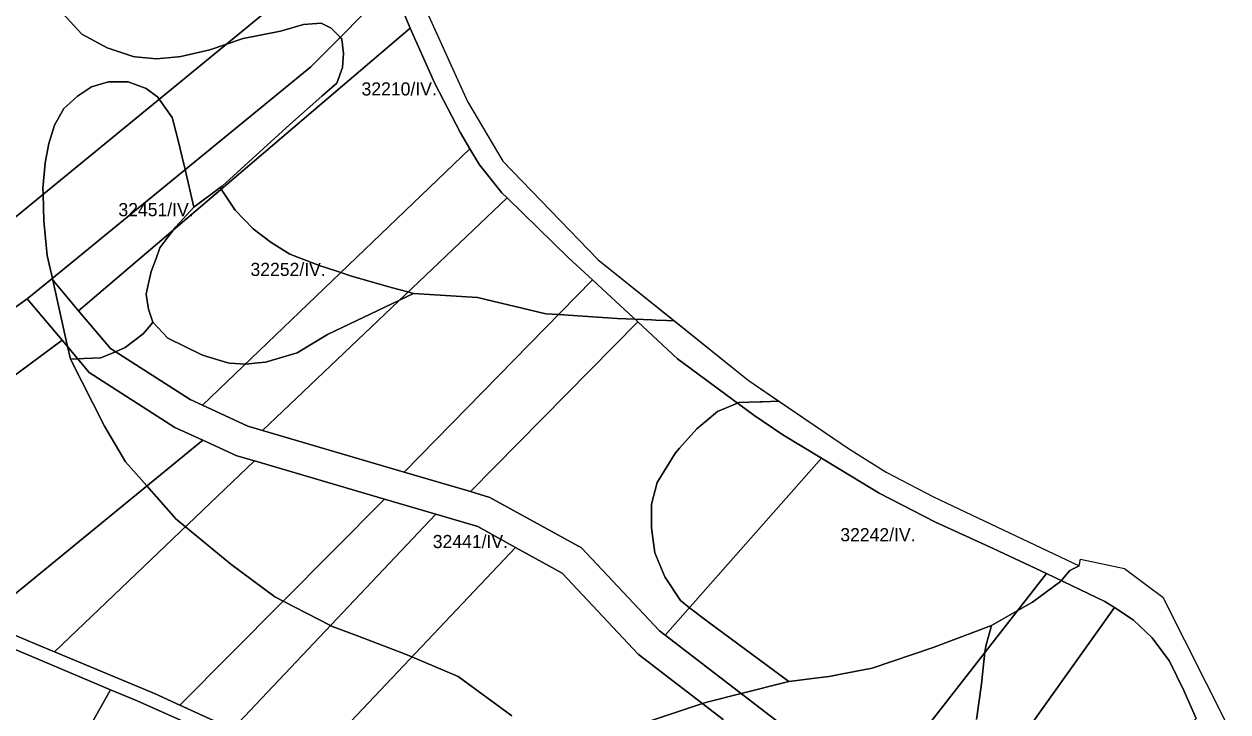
# Model space of a CAD drawing. Extents: x -522079 to -518833, y -1142400 to -1139961.
# Drawn here: x -520002.4 to -519544.3, y -1140913.1 to -1140651.2 of the extents above; entities that cross this region are included whole.
import ezdxf

# ---------------------------------------------------------------- set-up
doc = ezdxf.new("R2010")
doc.units = 0
for name, color, linetype in [('95560013', 7, 'Continuous'), ('95610013', 7, 'Continuous'), ('95640013', 7, 'Continuous'), ('95660013', 7, 'Continuous')]:
    doc.layers.add(name, color=color, linetype=linetype)

msp = doc.modelspace()

# ---------------------------------------------------------------- linework, layer by layer
at = {"layer": '95560013'}
for points in [[(-519911.88, -1140647.84), (-520013.2, -1140730.8), (-520072.01, -1140664.71), (-520082.56, -1140649.64), (-519886.24, -1140527.38), (-519882.2, -1140547.1), (-519878.23, -1140567.62), (-519875.11, -1140585.42), (-519873.69, -1140593.69), (-519873.07, -1140596.47), (-519870.83, -1140606.54)], [(-519862.3, -1140636.3), (-519855.49, -1140652.85), (-519981.63, -1140760.4), (-519991.87, -1140748.27), (-519893.23, -1140667.47)], [(-519981.63, -1140760.4), (-519855.49, -1140652.85), (-519846.13, -1140673.83), (-519836.32, -1140692.64), (-519832.73, -1140698.73), (-519934.47, -1140796.36), (-519939.19, -1140794.19), (-519969.55, -1140774.7)], [(-519832.73, -1140698.73), (-519829.11, -1140704.83), (-519820.55, -1140715.47), (-519818.61, -1140717.36), (-519911.71, -1140805.9), (-519917.19, -1140804.28), (-519934.47, -1140796.36)], [(-519911.71, -1140805.9), (-519818.61, -1140717.36), (-519795.23, -1140740.19), (-519786.12, -1140748.61), (-519857.7, -1140821.8)], [(-519857.7, -1140821.8), (-519786.12, -1140748.61), (-519782.42, -1140752.04), (-519768.84, -1140764.57), (-519832.56, -1140829.21)], [(-520001.24, -1140755.77), (-519987.93, -1140771.54), (-520091.34, -1140848.28), (-520106.23, -1140841.79), (-520119.77, -1140834.99), (-520068.52, -1140802.68), (-520010.06, -1140762.16)], [(-519698.98, -1140816.54), (-519758.42, -1140883.91), (-519760.64, -1140882.2), (-519790.25, -1140850.67), (-519825.13, -1140831.39), (-519832.56, -1140829.21), (-519768.84, -1140764.57), (-519753.73, -1140778.67), (-519724.7, -1140800.07), (-519713.71, -1140807.66)], [(-520091.34, -1140848.28), (-519987.93, -1140771.54), (-519977.56, -1140783.82), (-519944.96, -1140804.75), (-519934.39, -1140809.6), (-520018.57, -1140878.52), (-520022.3, -1140876.95), (-520034.41, -1140872.06), (-520067.09, -1140858.86)], [(-519934.39, -1140809.6), (-519921.41, -1140815.55), (-519914.69, -1140817.53), (-519990.79, -1140890.22), (-519997.49, -1140887.4), (-520018.57, -1140878.52)], [(-519758.42, -1140883.91), (-519698.98, -1140816.54), (-519677.02, -1140829.78), (-519655.55, -1140840.89), (-519633.63, -1140850.83), (-519613.39, -1140860.38), (-519678.04, -1140943.34), (-519697.68, -1140930.5)], [(-519990.79, -1140890.22), (-519914.69, -1140817.53), (-519865.19, -1140832.11), (-519943.08, -1140910.55), (-519952.82, -1140906.1)], [(-519865.19, -1140832.11), (-519845.71, -1140837.84), (-519923.13, -1140919.66), (-519943.08, -1140910.55)], [(-519923.13, -1140919.66), (-519845.71, -1140837.84), (-519829.78, -1140842.53), (-519815.37, -1140850.5), (-519893.61, -1140933.19), (-519907.29, -1140926.89)], [(-519815.37, -1140850.5), (-519797.7, -1140860.26), (-519768.72, -1140891.13), (-519736.43, -1140915.9), (-519792.75, -1140975.43), (-519809.71, -1140968.63), (-519858.03, -1140948.23), (-519890.83, -1140934.46), (-519893.61, -1140933.19)], [(-519654.13, -1140967.02), (-519587.52, -1140873.31), (-519580.34, -1140878), (-519573.15, -1140884.93), (-519566.48, -1140893.71), (-519561.03, -1140904.86), (-519556.41, -1140915.6), (-519632.87, -1140997.67), (-519645.74, -1140981.03)]]:
    msp.add_lwpolyline(points, close=True, dxfattribs=at)
at = {"layer": '95610013'}
for points in [[(-519862.3, -1140636.3), (-519893.23, -1140667.47), (-519991.87, -1140748.27), (-520001.24, -1140755.77), (-520010.06, -1140762.16), (-520068.52, -1140802.68), (-520119.77, -1140834.99), (-520149.6, -1140820.02), (-520083.41, -1140780.15), (-520025.44, -1140739.97), (-520022.9, -1140738.15), (-520013.2, -1140730.8), (-519911.88, -1140647.84), (-519870.83, -1140606.54), (-519868.76, -1140615.85)], [(-519587.52, -1140873.31), (-519654.13, -1140967.02), (-519662.03, -1140953.81), (-519678.04, -1140943.34), (-519613.39, -1140860.38), (-519591.11, -1140871.05)], [(-520022.73, -1140882.19), (-519999.48, -1140892), (-519969.45, -1140904.62), (-520002.28, -1140962.91), (-520009.84, -1140957.29), (-520015.17, -1140949.95), (-520029.76, -1140941.98), (-520046.33, -1140932.29), (-520051.93, -1140931.48), (-520055.67, -1140929.56)], [(-519969.45, -1140904.62), (-519959.29, -1140908.89), (-519927.83, -1140922.94), (-519916.21, -1140928.63), (-519943.51, -1140985.08), (-519947.03, -1140986.05), (-519959.93, -1140985.31), (-519965.47, -1140973.69), (-519974.08, -1140974.02), (-519986.94, -1140971.3), (-519999.3, -1140964.63), (-520002.28, -1140962.91)]]:
    msp.add_lwpolyline(points, close=True, dxfattribs=at)
at = {"layer": '95640013'}
for points in [[(-519855.18, -1140633.03), (-519833.7, -1140680.7), (-519820.17, -1140703.4), (-519783.91, -1140740.96), (-519726.89, -1140786.75), (-519688.67, -1140812.79), (-519674.4, -1140821.79), (-519656.36, -1140831.22), (-519600.86, -1140857.49), (-519600.42, -1140854.95), (-519583.72, -1140858.5), (-519575.54, -1140864.6), (-519569.14, -1140869.38), (-519544.31, -1140918.54)], [(-519556.41, -1140915.6), (-519561.03, -1140904.86), (-519566.48, -1140893.71), (-519573.15, -1140884.93), (-519580.34, -1140878), (-519587.52, -1140873.31), (-519591.11, -1140871.05), (-519613.39, -1140860.38), (-519633.63, -1140850.83), (-519655.55, -1140840.89), (-519677.02, -1140829.78), (-519698.98, -1140816.54), (-519713.71, -1140807.66), (-519724.7, -1140800.07), (-519753.73, -1140778.67), (-519768.84, -1140764.57), (-519782.42, -1140752.04), (-519786.12, -1140748.61), (-519795.23, -1140740.19), (-519818.61, -1140717.36), (-519820.55, -1140715.47), (-519829.11, -1140704.83), (-519832.73, -1140698.73), (-519836.32, -1140692.64), (-519846.13, -1140673.83), (-519855.49, -1140652.85), (-519862.3, -1140636.3)], [(-519736.43, -1140915.9), (-519768.72, -1140891.13), (-519797.7, -1140860.26), (-519815.37, -1140850.5), (-519829.78, -1140842.53), (-519845.71, -1140837.84), (-519865.19, -1140832.11), (-519914.69, -1140817.53), (-519921.41, -1140815.55), (-519934.39, -1140809.6), (-519944.96, -1140804.75), (-519977.56, -1140783.82), (-519987.93, -1140771.54), (-520001.24, -1140755.77), (-519991.87, -1140748.27), (-519981.63, -1140760.4), (-519969.55, -1140774.7), (-519939.19, -1140794.19), (-519934.47, -1140796.36), (-519917.19, -1140804.28), (-519911.71, -1140805.9), (-519857.7, -1140821.8), (-519832.56, -1140829.21), (-519825.13, -1140831.39), (-519790.25, -1140850.67), (-519760.64, -1140882.2), (-519758.42, -1140883.91), (-519697.68, -1140930.5)], [(-520018.57, -1140878.52), (-519997.49, -1140887.4), (-519990.79, -1140890.22), (-519952.82, -1140906.1), (-519943.08, -1140910.55), (-519923.13, -1140919.66)], [(-519927.83, -1140922.94), (-519959.29, -1140908.89), (-519969.45, -1140904.62), (-519999.48, -1140892), (-520022.73, -1140882.19)]]:
    msp.add_lwpolyline(points, dxfattribs=at)
at = {"layer": '95660013'}
for points in [[(-519855.18, -1140633.03), (-519839.36, -1140668.14), (-519833.7, -1140680.7), (-519820.17, -1140703.4), (-519783.91, -1140740.96), (-519754.92, -1140764.24), (-519757.79, -1140764.12), (-519761.97, -1140763.94), (-519763.7, -1140763.87), (-519769.86, -1140763.63), (-519776.69, -1140763.36), (-519799.05, -1140761.83), (-519803.86, -1140761.5), (-519829.8, -1140755.31), (-519854.23, -1140753.74), (-519856.3, -1140753.2), (-519862.74, -1140751.53), (-519878.13, -1140747.12), (-519881.86, -1140745.87), (-519888.11, -1140743.78), (-519889.68, -1140743.26), (-519901.22, -1140738.85), (-519908.36, -1140734.44), (-519915.23, -1140729.2), (-519922.1, -1140722.03), (-519927.37, -1140714.14), (-519927.8, -1140713.5), (-519927.05, -1140712.94), (-519901.22, -1140689.5), (-519889.13, -1140678.75), (-519883.36, -1140673.79), (-519881.16, -1140667.73), (-519880.88, -1140662.49), (-519881.43, -1140656.97), (-519882.12, -1140656.28), (-519885.55, -1140652.84), (-519889.4, -1140650.91), (-519896, -1140651.46), (-519904.79, -1140653.94), (-519919.08, -1140656.7), (-519925.38, -1140658.9), (-519931.72, -1140661.11), (-519942.72, -1140663.59), (-519943.73, -1140663.68), (-519952.06, -1140664.42), (-519960.12, -1140663.66), (-519960.85, -1140663.59), (-519970.75, -1140660.28), (-519980.36, -1140655.04), (-519987.78, -1140647.05)], [(-519987.78, -1140647.05), (-519980.36, -1140655.04), (-519970.75, -1140660.28), (-519960.85, -1140663.59), (-519960.12, -1140663.66), (-519952.06, -1140664.42), (-519943.73, -1140663.68), (-519942.72, -1140663.59), (-519931.72, -1140661.11), (-519925.38, -1140658.9), (-519919.08, -1140656.7), (-519904.79, -1140653.94), (-519896, -1140651.46), (-519889.4, -1140650.91), (-519885.55, -1140652.84), (-519882.12, -1140656.28), (-519881.43, -1140656.97), (-519880.88, -1140662.49), (-519881.16, -1140667.73), (-519883.36, -1140673.79), (-519889.13, -1140678.75), (-519901.22, -1140689.5), (-519927.05, -1140712.94), (-519927.8, -1140713.5), (-519937.77, -1140720.93), (-519941.07, -1140706.66), (-519942.17, -1140701.91), (-519944.02, -1140694.6), (-519946.01, -1140686.75), (-519950.94, -1140679.82), (-519951.51, -1140679.03), (-519955.91, -1140675.72), (-519962.78, -1140673.24), (-519970.2, -1140673.24), (-519976.79, -1140675.17), (-519982.01, -1140678.75), (-519986.11, -1140682.43), (-519987.24, -1140683.44), (-519990.81, -1140689.78), (-519993.01, -1140696.67), (-519994.38, -1140704.11), (-519994.62, -1140706.96), (-519995.21, -1140713.76), (-519995.16, -1140716.02), (-519994.93, -1140726.17), (-519993.56, -1140739.4), (-519991.62, -1140748.07), (-519991.47, -1140748.74), (-519985.83, -1140774.02), (-519984.76, -1140778.82), (-519971.81, -1140804.24), (-519963.78, -1140817.86), (-519955.69, -1140827.03), (-519944.64, -1140839.54), (-519940.94, -1140842.6), (-519923.65, -1140856.89), (-519906.98, -1140869.27), (-519903.75, -1140870.94), (-519885.8, -1140880.2), (-519885.37, -1140880.43), (-519875.57, -1140884.14), (-519857.58, -1140890.95), (-519854.78, -1140892.15), (-519837.21, -1140899.63), (-519816.83, -1140914.5)], [(-519816.83, -1140914.5), (-519837.21, -1140899.63), (-519854.78, -1140892.15), (-519857.58, -1140890.95), (-519875.57, -1140884.14), (-519885.37, -1140880.43), (-519885.8, -1140880.2), (-519903.75, -1140870.94), (-519906.98, -1140869.27), (-519923.65, -1140856.89), (-519940.94, -1140842.6), (-519944.64, -1140839.54), (-519955.69, -1140827.03), (-519963.78, -1140817.86), (-519971.81, -1140804.24), (-519984.76, -1140778.82), (-519982.44, -1140778.71), (-519981.89, -1140778.69), (-519979.47, -1140778.57), (-519973.22, -1140778.27), (-519967.6, -1140775.95), (-519963.88, -1140774.41), (-519957.01, -1140769.17), (-519954.08, -1140765.56), (-519953.43, -1140764.76), (-519947.66, -1140770.83), (-519934.75, -1140777.17), (-519932.87, -1140777.75), (-519924.85, -1140780.2), (-519924.04, -1140780.27), (-519918.19, -1140780.74), (-519917.98, -1140780.75), (-519913.45, -1140780.25), (-519910.56, -1140779.93), (-519898.47, -1140776.34), (-519886.93, -1140769.45), (-519859.55, -1140756.3), (-519854.23, -1140753.74), (-519829.8, -1140755.31), (-519803.86, -1140761.5), (-519799.05, -1140761.83), (-519776.69, -1140763.36), (-519769.86, -1140763.63), (-519763.7, -1140763.87), (-519761.97, -1140763.94), (-519757.79, -1140764.12), (-519754.92, -1140764.24), (-519726.89, -1140786.75), (-519715.13, -1140794.76), (-519721.58, -1140795.04), (-519721.96, -1140795.05), (-519722.47, -1140795.07), (-519730.43, -1140795.31), (-519730.89, -1140795.51), (-519738.57, -1140798.76), (-519746.4, -1140805.36), (-519752.93, -1140812.67), (-519754.54, -1140814.47), (-519761.43, -1140825.78), (-519763.62, -1140833.95), (-519763.62, -1140843.06), (-519762.37, -1140852.48), (-519758.61, -1140861.59), (-519752.66, -1140870.7), (-519749.14, -1140873.4), (-519742.01, -1140878.86), (-519711.33, -1140901.48), (-519729.55, -1140906.05), (-519742.64, -1140909.34), (-519744.27, -1140909.88), (-519765.19, -1140916.87)], [(-519639.93, -1140915.93), (-519638.05, -1140902.43), (-519637.39, -1140896.31), (-519636.75, -1140890.35), (-519636.49, -1140887.98), (-519634.3, -1140880.12), (-519624.48, -1140874.6), (-519618.64, -1140871.33), (-519607.99, -1140863.48), (-519607.68, -1140863.11), (-519606.59, -1140861.83), (-519604.41, -1140859.25), (-519600.86, -1140857.49), (-519600.68, -1140856.47), (-519600.64, -1140856.22), (-519600.42, -1140854.95), (-519583.72, -1140858.5), (-519575.54, -1140864.6), (-519569.14, -1140869.38), (-519544.31, -1140918.54)], [(-519765.19, -1140916.87), (-519744.27, -1140909.88), (-519742.64, -1140909.34), (-519729.55, -1140906.05), (-519711.33, -1140901.48), (-519699.38, -1140900.02), (-519695.98, -1140899.6), (-519691.59, -1140898.75), (-519679.7, -1140896.45), (-519656.53, -1140888.6), (-519634.3, -1140880.12), (-519636.49, -1140887.98), (-519636.75, -1140890.35), (-519637.39, -1140896.31), (-519638.05, -1140902.43), (-519639.93, -1140915.93)]]:
    msp.add_lwpolyline(points, dxfattribs=at)
for points in [[(-519982.44, -1140778.71), (-519984.76, -1140778.82), (-519985.83, -1140774.02), (-519991.47, -1140748.74), (-519991.62, -1140748.07), (-519993.56, -1140739.4), (-519994.93, -1140726.17), (-519995.16, -1140716.02), (-519995.21, -1140713.76), (-519994.62, -1140706.96), (-519994.38, -1140704.11), (-519993.01, -1140696.67), (-519990.81, -1140689.78), (-519987.24, -1140683.44), (-519986.11, -1140682.43), (-519982.01, -1140678.75), (-519976.79, -1140675.17), (-519970.2, -1140673.24), (-519962.78, -1140673.24), (-519955.91, -1140675.72), (-519951.51, -1140679.03), (-519950.94, -1140679.82), (-519946.01, -1140686.75), (-519944.02, -1140694.6), (-519942.17, -1140701.91), (-519941.07, -1140706.66), (-519937.77, -1140720.93), (-519944.64, -1140728.37), (-519945.67, -1140729.74), (-519946.35, -1140730.63), (-519947.66, -1140732.36), (-519950.69, -1140736.37), (-519952.15, -1140740.42), (-519953.98, -1140745.47), (-519955.11, -1140750.48), (-519955.91, -1140754.01), (-519955.54, -1140756.57), (-519955.08, -1140759.8), (-519953.43, -1140764.76), (-519954.08, -1140765.56), (-519957.01, -1140769.17), (-519963.88, -1140774.41), (-519967.6, -1140775.95), (-519973.22, -1140778.27), (-519979.47, -1140778.57), (-519981.89, -1140778.69)], [(-519913.45, -1140780.25), (-519917.98, -1140780.75), (-519918.19, -1140780.74), (-519924.04, -1140780.27), (-519924.85, -1140780.2), (-519932.87, -1140777.75), (-519934.75, -1140777.17), (-519947.66, -1140770.83), (-519953.43, -1140764.76), (-519955.08, -1140759.8), (-519955.54, -1140756.57), (-519955.91, -1140754.01), (-519955.11, -1140750.48), (-519953.98, -1140745.47), (-519952.15, -1140740.42), (-519950.69, -1140736.37), (-519947.66, -1140732.36), (-519946.35, -1140730.63), (-519945.67, -1140729.74), (-519944.64, -1140728.37), (-519937.77, -1140720.93), (-519927.8, -1140713.5), (-519927.37, -1140714.14), (-519922.1, -1140722.03), (-519915.23, -1140729.2), (-519908.36, -1140734.44), (-519901.22, -1140738.85), (-519889.68, -1140743.26), (-519888.11, -1140743.78), (-519881.86, -1140745.87), (-519878.13, -1140747.12), (-519862.74, -1140751.53), (-519856.3, -1140753.2), (-519854.23, -1140753.74), (-519859.55, -1140756.3), (-519886.93, -1140769.45), (-519898.47, -1140776.34), (-519910.56, -1140779.93)], [(-519600.86, -1140857.49), (-519604.41, -1140859.25), (-519606.59, -1140861.83), (-519607.68, -1140863.11), (-519607.99, -1140863.48), (-519618.64, -1140871.33), (-519624.48, -1140874.6), (-519634.3, -1140880.12), (-519656.53, -1140888.6), (-519679.7, -1140896.45), (-519691.59, -1140898.75), (-519695.98, -1140899.6), (-519699.38, -1140900.02), (-519711.33, -1140901.48), (-519742.01, -1140878.86), (-519749.14, -1140873.4), (-519752.66, -1140870.7), (-519758.61, -1140861.59), (-519762.37, -1140852.48), (-519763.62, -1140843.06), (-519763.62, -1140833.95), (-519761.43, -1140825.78), (-519754.54, -1140814.47), (-519752.93, -1140812.67), (-519746.4, -1140805.36), (-519738.57, -1140798.76), (-519730.89, -1140795.51), (-519730.43, -1140795.31), (-519722.47, -1140795.07), (-519721.96, -1140795.05), (-519721.58, -1140795.04), (-519715.13, -1140794.76), (-519688.67, -1140812.79), (-519674.4, -1140821.79), (-519656.36, -1140831.22)]]:
    msp.add_lwpolyline(points, close=True, dxfattribs=at)

# ---------------------------------------------------------------- texts
for s, rotation, p in [('32210/IV.', 0, (-519873.97, -1140678.43)), ('32451/IV.', 360, (-519966.49, -1140724.37)), ('32252/IV.', 0, (-519916.23, -1140747.13)), ('32242/IV.', 360, (-519691.8, -1140848.12)), ('32441/IV.', 360, (-519846.87, -1140850.71))]:
    msp.add_text(s, height=5, rotation=rotation, dxfattribs=at).set_placement(p)

doc.saveas('drawing.dxf')
